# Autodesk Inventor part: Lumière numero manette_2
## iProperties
Created: 2010-07
Part Number: Lumière numero manette_2
Document SubType Name: Modeling
Designer: eric
Density: 1 g/cm^3
Author: eric
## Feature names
1. Base1
